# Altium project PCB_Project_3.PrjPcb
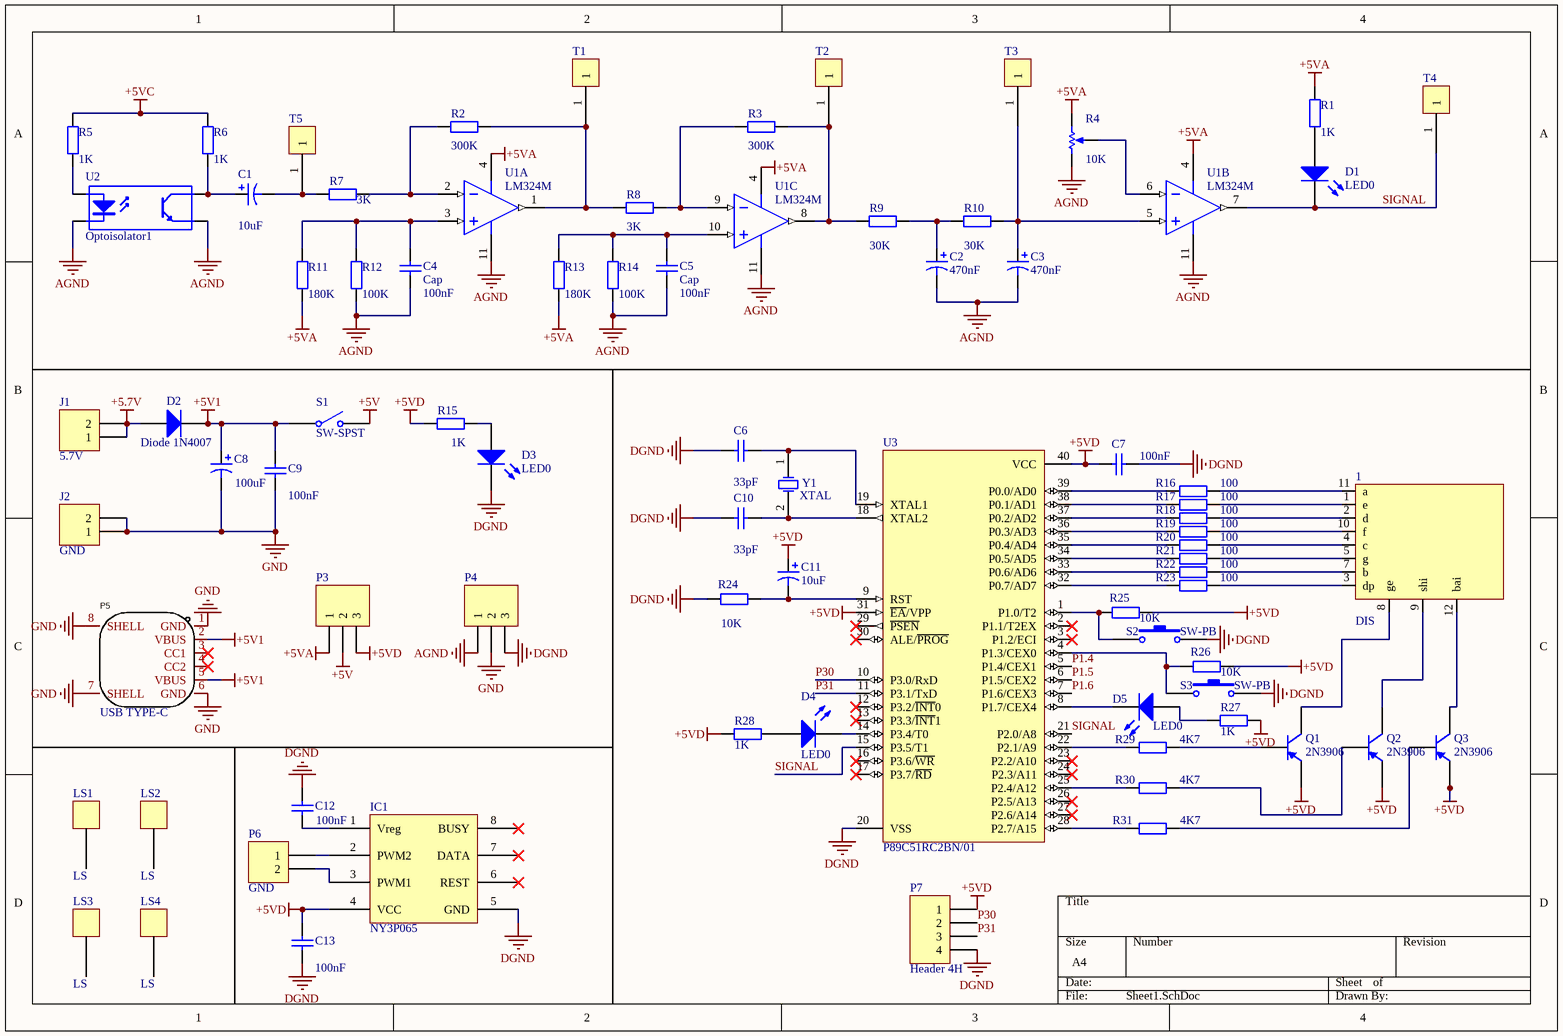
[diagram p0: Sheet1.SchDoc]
1 sheet, 77 parts. Net scope: global (net labels, ports and power ports of the same name join across sheets).
Board file: PCB1.PcbDoc

## Sheet Sheet1.SchDoc
size A4; SheetNumber: 1; SheetTotal: 1

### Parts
1  DIS  [SMG]
C1  value 10uF  [CD-0.2T]  (hidden comment: Cap Pol1)
C2  value 470nF  [CD-0.2T]  (hidden comment: Cap Pol1)
C3  value 470nF  [CD-0.2T]  (hidden comment: Cap Pol1)
C4  Cap  value 100nF  [C-0.1]
C5  Cap  value 100nF  [C-0.1]
C6  value 33pF  [C-0.1]  (hidden comment: Cap)
C7  value 100nF  [C-0.1]  (hidden comment: Cap)
C8  value 100uF  [CD-0.2T]  (hidden comment: Cap Pol1)
C9  value 100nF  [C-0.1]  (hidden comment: Cap)
C10  value 33pF  [C-0.1]  (hidden comment: Cap)
C11  value 10uF  [CD-0.2T]  (hidden comment: Cap Pol1)
C12  value 100nF  [C-0.1]  (hidden comment: Cap)
C13  value 100nF  [C-0.1]  (hidden comment: Cap)
D1  LED0  [LED3]
D2  Diode 1N4007  [DO-41]
D3  LED0  [LED3]
D4  LED0  [LED3]
D5  LED0  [LED3]
IC1  NY3P065  [SOP8]
J1  5.7V  [SIP2]
J2  GND  [SIP2]
LS1  LS  [SOLID]
LS2  LS  [SOLID]
LS3  LS  [SOLID]
LS4  LS  [SOLID]
P3  Header 3  [HDR1X3]  (value not drawn)
P4  Header 3  [HDR1X3]  (value not drawn)
P5  USB TYPE-C  [USBTYPEC6]
P6  GND  [HDR1X2]
P7  Header 4H  [SIP4]
Q1  2N3906  [TO92C]
Q2  2N3906  [TO92C]
Q3  2N3906  [TO92C]
R1  value 1K  [R-0.3]  (hidden comment: Res2)
R2  value 300K  [R-0.3]  (hidden comment: Res2)
R3  value 300K  [R-0.3]  (hidden comment: Res2)
R4  value 10K  [3362P]  (hidden comment: RPot)
R5  value 1K  [R-0.3]  (hidden comment: Res2)
R6  value 1K  [R-0.3]  (hidden comment: Res2)
R7  value 3K  [R-0.3]  (hidden comment: Res2)
R8  value 3K  [R-0.3]  (hidden comment: Res2)
R9  value 30K  [R-0.3]  (hidden comment: Res2)
R10  value 30K  [R-0.3]  (hidden comment: Res2)
R11  value 180K  [R-0.3]  (hidden comment: Res2)
R12  value 100K  [R-0.3]  (hidden comment: Res2)
R13  value 180K  [R-0.3]  (hidden comment: Res2)
R14  value 100K  [R-0.3]  (hidden comment: Res2)
R15  value 1K  [R-0.3]  (hidden comment: Res2)
R16  value 100  [R-0.3]  (hidden comment: Res2)
R17  value 100  [R-0.3]  (hidden comment: Res2)
R18  value 100  [R-0.3]  (hidden comment: Res2)
R19  value 100  [R-0.3]  (hidden comment: Res2)
R20  value 100  [R-0.3]  (hidden comment: Res2)
R21  value 100  [R-0.3]  (hidden comment: Res2)
R22  value 100  [R-0.3]  (hidden comment: Res2)
R23  value 100  [R-0.3]  (hidden comment: Res2)
R24  value 10K  [R-0.3]  (hidden comment: Res2)
R25  value 10K  [R-0.3]  (hidden comment: Res2)
R26  value 10K  [R-0.3]  (hidden comment: Res2)
R27  value 1K  [R-0.3]  (hidden comment: Res2)
R28  value 1K  [R-0.3]  (hidden comment: Res2)
R29  value 4K7  [R-0.3]  (hidden comment: Res2)
R30  value 4K7  [R-0.3]  (hidden comment: Res2)
R31  value 4K7  [R-0.3]  (hidden comment: Res2)
S1  SW-SPST  [ONOFF]
S2  SW-PB  [KEY]
S3  SW-PB  [KEY]
T1  TEST  [TP]  (value not drawn)
T2  TEST  [TP]  (value not drawn)
T3  TEST  [TP]  (value not drawn)
T4  TEST  [TP]  (value not drawn)
T5  TEST  [TP]  (value not drawn)
U1  LM324M  [M14A_N]  (parts A,B,C of 4)
U2  Optoisolator1  [SEN]
U3  P89C51RC2BN/01  [SOT129-1]
Y1  XTAL  [JZ]

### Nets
+5.7V: D2.1(A) J1.1 J1.2
+5V: P3.2 S1.2(NO)
+5V1: C8.1 C9.2 D2.2(K) P5.2(VBUS) P5.5(VBUS) S1.1(COMMON)
+5VA: P3.1 R1.2 R4.2(BOT) R11.2 R13.2 U1.4(V+)
+5VC: R5.2 R6.2
+5VD: C7.2 C11.1 C13.2 IC1.4(VCC) P3.3 P7.1 Q1.1(E) Q2.1(E) Q3.1(E) R15.2 R25.1 R26.1 R27.2 R28.2 U3.31(~{EA}/VPP) U3.40(VCC)
AGND: C2.2 C3.2 C4.1 C5.1 P4.1 R4.1(TOP) R12.2 R14.2 U1.11(GND) U2.2(K) U2.3(E)
DGND: C6.2 C7.1 C10.2 C12.2 C13.1 D3.2(K) IC1.5(GND) P4.3 P7.4 R24.2 S2.2 S3.2 U3.20(VSS)
GND: C8.2 C9.1 J2.1 J2.2 P4.2 P5.1(GND) P5.6(GND) P5.7(SHELL) P5.8(SHELL)
P1.4: U3.5(P1.4/CEX1)
P1.5: U3.6(P1.5/CEX2)
P1.6: U3.7(P1.6/CEX3)
P30: P7.2 U3.10(P3.0/RxD)
P31: P7.3 U3.11(P3.1/TxD)
SIGNAL: D1.2(K) T4.1 U1.7(OUT2) U3.15(P3.5/T1) U3.21(P2.0/A8)
Net1_1: 1.1(e) R17.1
Net1_2: 1.2(d) R18.1
Net1_3: 1.3(dp) R23.1
Net1_4: 1.4(c) R20.1
Net1_5: 1.5(g) R21.1
Net1_7: 1.7(b) R22.1
Net1_8: 1.8(ge) Q1.3(C)
Net1_9: 1.9(shi) Q2.3(C)
Net1_10: 1.10(f) R19.1
Net1_11: 1.11(a) R16.1
Net1_12: 1.12(bai) Q3.3(C)
NetC1_1: C1.1 R6.1 U2.4(C)
NetC1_2: C1.2 R7.2 T5.1
NetC2_1: C2.1 R9.2 R10.1
NetC3_1: C3.1 R10.2 T3.1 U1.5(IN2+)
NetC4_2: C4.2 R11.1 R12.1 U1.3(IN1+)
NetC5_2: C5.2 R13.1 R14.1 U1.10(IN3+)
NetC6_1: C6.1 U3.19(XTAL1) Y1.1(OSC1)
NetC10_1: C10.1 U3.18(XTAL2) Y1.2(OSC2)
NetC11_2: C11.2 R24.1 U3.9(RST)
NetC12_1: C12.1 IC1.1(Vreg)
NetD1_1: D1.1(A) R1.1
NetD3_1: D3.1(A) R15.1
NetD4_1: D4.1(A) R28.1
NetD4_2: D4.2(K) U3.14(P3.4/T0)
NetD5_1: D5.1(A) R27.1
NetD5_2: D5.2(K) U3.8(P1.7/CEX4)
NetIC1_2: IC1.2(PWM2) P6.1
NetIC1_3: IC1.3(PWM1) P6.2
NetQ1_2: Q1.2(B) R29.1
NetQ2_2: Q2.2(B) R30.1
NetQ3_2: Q3.2(B) R31.2
NetR2_1: R2.1 R8.1 T1.1 U1.1(OUT1)
NetR2_2: R2.2 R7.1 U1.2(IN1-)
NetR3_1: R3.1 R9.1 T2.1 U1.8(OUT3)
NetR3_2: R3.2 R8.2 U1.9(IN3-)
NetR4_3: R4.3(TAP) U1.6(IN2-)
NetR5_1: R5.1 U2.1(A)
NetR16_2: R16.2 U3.39(P0.0/AD0)
NetR17_2: R17.2 U3.38(P0.1/AD1)
NetR18_2: R18.2 U3.37(P0.2/AD2)
NetR19_2: R19.2 U3.36(P0.3/AD3)
NetR20_2: R20.2 U3.35(P0.4/AD4)
NetR21_2: R21.2 U3.34(P0.5/AD5)
NetR22_2: R22.2 U3.33(P0.6/AD6)
NetR23_2: R23.2 U3.32(P0.7/AD7)
NetR25_2: R25.2 S2.1 U3.1(P1.0/T2)
NetR26_2: R26.2 S3.1 U3.4(P1.3/CEX0)
NetR29_2: R29.2 U3.22(P2.1/A9)
NetR30_2: R30.2 U3.25(P2.4/A12)
NetR31_1: R31.1 U3.28(P2.7/A15)

Not connected (* = marked no-connect by the designer): IC1 6(REST)* 7(DATA)* 8(BUSY)*; P5 3(CC1)* 4(CC2)*; U3 2(P1.1/T2EX)* 3(P1.2/ECI)* 12(P3.2/~{INT}0)* 13(P3.3/~{INT}1)* 16(P3.6/~{WR})* 17(P3.7/~{RD})* 23(P2.2/A10)* 24(P2.3/A11)* 26(P2.5/A13)* 27(P2.6/A14)* 29(~{PSEN})* 30(ALE/~{PROG})*

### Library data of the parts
C1-C3 C8 C11 = Cap Pol1: Polarized Capacitor (Radial)
C4-C7 C9 C10 C12 C13 = Cap: Capacitor
D1 D3-D5 = LED0: Typical INFRARED GaAs LED
D2 = Diode 1N4007: 1 Amp General Purpose Rectifier
IC1 = SOUND
J1 J2 P6 = Header 2: Header, 2-Pin
LS1-LS4 = LS: solid
P3 P4 = Header 3: Header, 3-Pin
P5 = USB TYPE-C 6P: Symbol: TYPE-C 6P CB1.6(073); Add into BOM: yes; Number of Ports: 1; Number of Contacts: 6P; Current Rating - Power (Max): 5A
P7 = Header 4H: Header, 4-Pin, Right Angle
Q1-Q3 = 2N3906: PNP General Purpose Amplifier
R1-R3 R5-R31 = Res2: Resistor
R4 = RPot: Potentiometer; Sim Note: Enter the Resistance value and the set point into parameter fields.; Set Position: 0.5
S1 = SW-SPST: Single-Pole, Single-Throw Switch
S2 S3 = SW-PB: Switch
U1 = LM324M: Low Power Quad Operational Amplifier; Manufacturer: National Semiconductor; CompType: Amplifiers; PackageTopMarking: NSUZXYTT*LM324M
U2 = Optoisolator1: 4-Pin Phototransistor Optocoupler
U3 = P89C51RC2BN/01: 80C51 8-Bit Flash Microcontroller Family, 32 kB ISP/IAP Flash with 512 B RAM.
Y1 = XTAL: Crystal Oscillator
